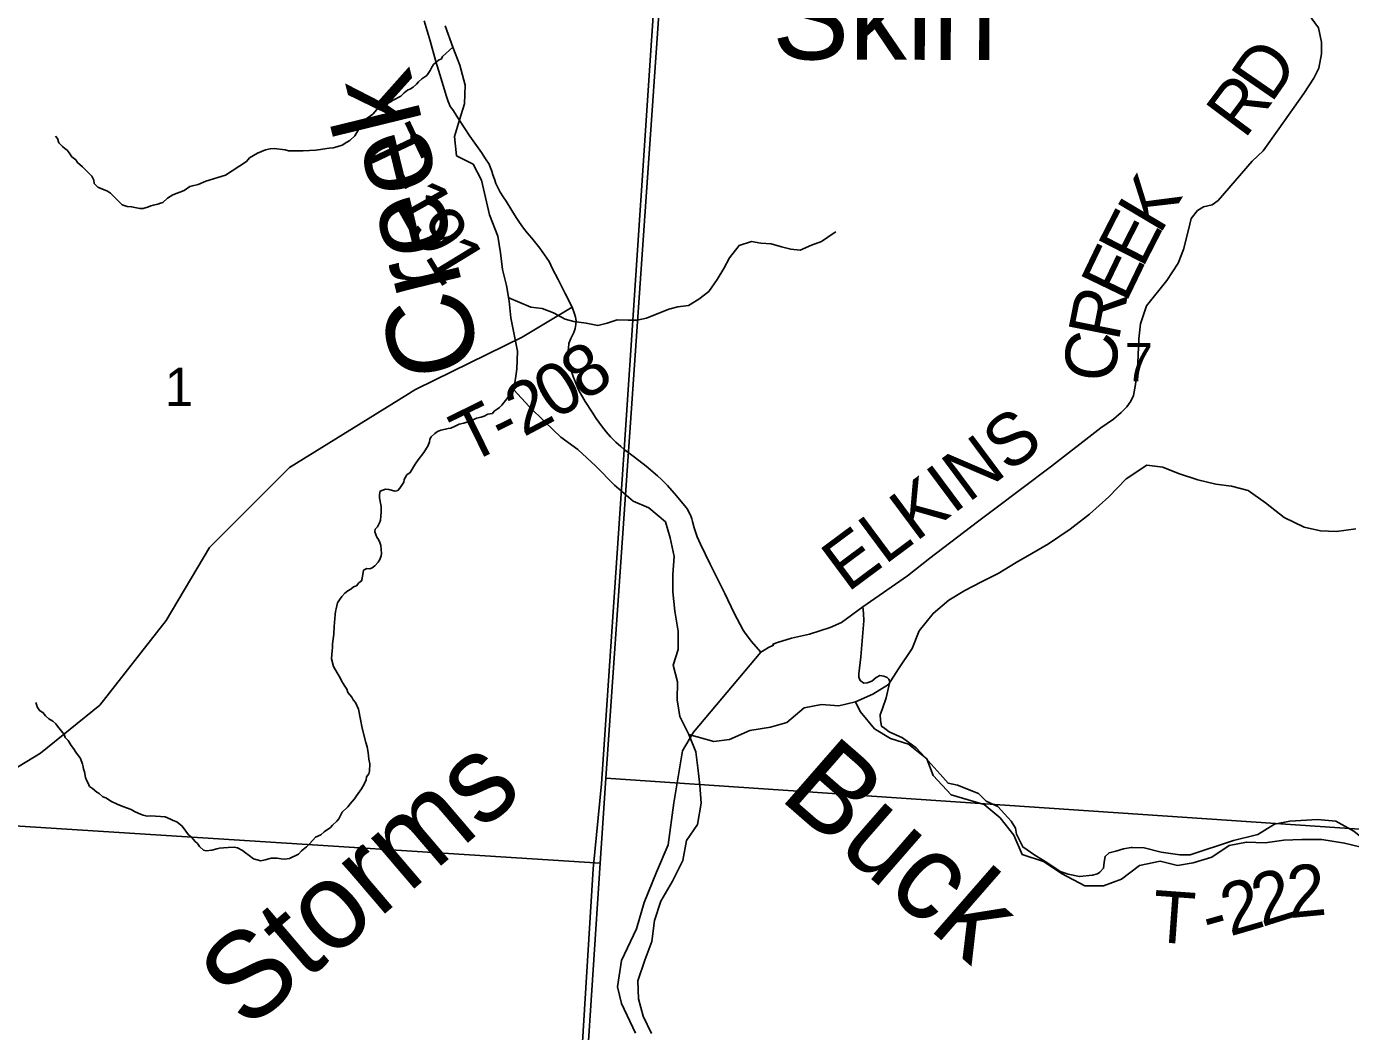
# Model space of a CAD drawing. Extents: x 0 to 34, y 0 to 22.
# Drawn here: x 6.132 to 7.584, y 18.121 to 19.223 of the extents above; entities that cross this region are included whole.
import ezdxf

# ---------------------------------------------------------------- set-up
doc = ezdxf.new("R2010")
doc.units = 0
for name, color, linetype in [('GM_X_Corporation', 7, 'Continuous'), ('GM_X_County_Road', 7, 'Continuous'), ('GM_X_County_Road_Text', 7, 'Continuous'), ('GM_X_Minor_River', 7, 'Continuous'), ('GM_X_Minor_River_Text', 7, 'Continuous'), ('GM_X_Section_Text', 7, 'Continuous'), ('GM_X_Township_Road', 7, 'Continuous'), ('GM_X_Township_Road_Text', 7, 'Continuous')]:
    doc.layers.add(name, color=color, linetype=linetype)

msp = doc.modelspace()

# ---------------------------------------------------------------- linework, layer by layer
at = {"layer": 'GM_X_Corporation'}
for points in [[(8.9, 16.2015), (8.9, 20.2763), (8.59, 20.3005), (8.3805, 20.3169), (8.0028, 20.34), (6.9032, 20.4198), (6.8961, 20.3303), (6.835, 19.4037), (6.824, 19.3005), (6.7876, 18.7583), (6.7629, 18.3924), (6.7536, 18.2991), (6.7043, 17.4985), (6.6962, 17.3669), (6.6852, 17.2401), (6.6249, 16.3344), (7.5782, 16.28), (7.7162, 16.2721), (7.873, 16.2628)], [(7.9347, 19.3346), (7.864, 18.3242), (6.7676, 18.3985), (6.8303, 19.3047), (6.8376, 19.4096)], [(5.8355, 19.3781), (6.8303, 19.3047), (6.7676, 18.3985), (6.7615, 18.3053), (5.775, 18.3681)], [(6.7676, 18.3985), (7.864, 18.3242), (7.7921, 17.3025), (6.6999, 17.3699), (6.7615, 18.3053)], [(5.775, 18.3681), (6.7615, 18.3053), (6.6999, 17.3699), (6.6918, 17.2464), (5.6845, 17.321)]]:
    msp.add_lwpolyline(points, close=True, dxfattribs=at)
msp.add_lwpolyline([(6.7043, 17.4985), (6.7536, 18.2991), (6.7629, 18.3924), (6.7876, 18.7583), (6.824, 19.3005), (6.5423, 19.3229), (5.9419, 19.3649), (5.6539, 19.3859), (5.0201, 19.4401), (4.8375, 19.4557), (3.8692, 19.5228), (3.8201, 19.5262), (3.0215, 19.5789), (2.5886, 19.6074), (2.105, 19.6393), (2.1, 19.6396), (2.1, 16.1353)], dxfattribs=at)
at = {"layer": 'GM_X_County_Road'}
msp.add_lwpolyline([(6.8001, 18.1189), (6.7846, 18.1516), (6.7804, 18.1699), (6.7846, 18.1988), (6.8014, 18.2333), (6.8098, 18.2622), (6.8231, 18.2953), (6.836, 18.3253), (6.8421, 18.3714), (6.8518, 18.4286), (6.8637, 18.4488), (6.9377, 18.5367), (6.9411, 18.539), (6.9461, 18.5417), (6.9514, 18.5442), (6.9508, 18.5454), (6.9559, 18.5472), (6.9712, 18.5519), (6.9908, 18.5563), (7.0136, 18.5638), (7.0259, 18.569), (7.0492, 18.5864), (7.0984, 18.6205), (7.1228, 18.6396), (7.175, 18.6794), (7.1957, 18.695), (7.2222, 18.715), (7.2563, 18.7407), (7.3104, 18.7827), (7.3242, 18.7919), (7.3326, 18.7994), (7.3389, 18.8057), (7.3432, 18.8118), (7.3461, 18.8181), (7.3484, 18.8299), (7.3507, 18.8535), (7.3521, 18.8803), (7.3536, 18.8964), (7.3603, 18.9163), (7.3827, 18.944), (7.3949, 18.9631), (7.401, 18.9781), (7.4065, 18.9998), (7.4095, 19.0121), (7.4163, 19.0209), (7.4228, 19.0247), (7.4323, 19.0271), (7.4391, 19.0318), (7.4762, 19.075), (7.4881, 19.0862), (7.5054, 19.1104), (7.533, 19.1492), (7.5438, 19.1658), (7.5493, 19.1767), (7.5523, 19.1927), (7.5522, 19.2055), (7.549, 19.2211), (7.5381, 19.2359)], dxfattribs=at)
at = {"layer": 'GM_X_Minor_River'}
for points in [[(6.6402, 19.0162), (6.6312, 19.0541), (6.6222, 19.0716), (6.604, 19.0808), (6.6018, 19.102), (6.6072, 19.1202), (6.6125, 19.1376), (6.6133, 19.1581), (6.6074, 19.1801), (6.5999, 19.1999), (6.5916, 19.2234)], [(6.5999, 19.1999), (6.5884, 19.1896), (6.5873, 19.187), (6.5842, 19.1855), (6.5815, 19.1833), (6.5788, 19.1807), (6.5769, 19.1781), (6.5749, 19.1743), (6.5714, 19.169), (6.566, 19.1653), (6.5622, 19.162), (6.5599, 19.1593), (6.5564, 19.156), (6.5534, 19.1541), (6.5503, 19.1527), (6.5465, 19.1497), (6.543, 19.146), (6.5346, 19.1419), (6.5311, 19.1397), (6.525, 19.1371), (6.522, 19.1368), (6.5189, 19.1342), (6.512, 19.1264), (6.5035, 19.1204), (6.5004, 19.1167), (6.4977, 19.1106), (6.4957, 19.108), (6.4926, 19.1028), (6.4868, 19.0975), (6.4838, 19.0957), (6.4784, 19.0924), (6.4727, 19.0906), (6.4685, 19.0895), (6.4643, 19.0892), (6.4522, 19.0875), (6.4495, 19.0868), (6.4359, 19.0862), (6.4264, 19.0864), (6.4226, 19.0861), (6.4196, 19.0861), (6.4162, 19.0873), (6.4041, 19.0887), (6.3996, 19.0884), (6.3946, 19.0873), (6.3858, 19.0837), (6.377, 19.0785), (6.3735, 19.0744), (6.3506, 19.0596), (6.3289, 19.0531), (6.3205, 19.0495), (6.3144, 19.048), (6.3117, 19.0473), (6.3052, 19.0429), (6.293, 19.0381), (6.2872, 19.0344), (6.2819, 19.0296), (6.2792, 19.0289), (6.2765, 19.0278), (6.2716, 19.0267), (6.2689, 19.026), (6.2662, 19.0249), (6.2605, 19.0231), (6.2567, 19.0232), (6.2477, 19.0249), (6.2428, 19.0253), (6.2375, 19.0269), (6.2308, 19.0335), (6.2245, 19.0397), (6.2211, 19.042), (6.2132, 19.0452), (6.2106, 19.0464), (6.2068, 19.0503), (6.2062, 19.0541), (6.204, 19.0583), (6.2017, 19.061), (6.1965, 19.066), (6.1939, 19.0687), (6.1883, 19.0734), (6.1865, 19.0764), (6.182, 19.0796), (6.1794, 19.0842), (6.1772, 19.0868), (6.1746, 19.0888), (6.172, 19.0911), (6.1679, 19.095), (6.1664, 19.0996), (6.1642, 19.1023)], [(6.8176, 18.1185), (6.8085, 18.1375), (6.8033, 18.1565), (6.8026, 18.1763), (6.8102, 18.199), (6.8179, 18.2195), (6.821, 18.2423), (6.8278, 18.2635), (6.8408, 18.2855), (6.8522, 18.3082), (6.856, 18.3302), (6.8682, 18.3476), (6.8721, 18.3712), (6.8706, 18.3909), (6.8684, 18.4099), (6.8662, 18.4273), (6.8587, 18.4463), (6.8489, 18.4661), (6.8459, 18.4843), (6.846, 18.5041), (6.8415, 18.5223), (6.8469, 18.5397), (6.8469, 18.5595), (6.8432, 18.5815), (6.841, 18.6028), (6.841, 18.6217), (6.8426, 18.6415), (6.8381, 18.662), (6.8329, 18.6794), (6.8148, 18.6947), (6.7974, 18.7023), (6.777, 18.7198), (6.7566, 18.7404), (6.737, 18.7587), (6.7181, 18.7724), (6.7008, 18.7891), (6.6834, 18.8059), (6.6668, 18.8241), (6.6699, 18.8469), (6.6707, 18.8666), (6.6633, 18.903), (6.6618, 18.9213), (6.6588, 18.9387), (6.6544, 18.9562), (6.6521, 18.9744), (6.6492, 18.9926), (6.6402, 19.0162)], [(6.6611, 18.9252), (6.6854, 18.9147), (6.6979, 18.9135), (6.7104, 18.9086), (6.7229, 18.9018), (6.7327, 18.8991), (6.746, 18.8972), (6.7589, 18.8949), (6.7691, 18.8972), (6.7801, 18.901), (6.7922, 18.9006), (6.802, 18.9006), (6.8122, 18.9029), (6.8368, 18.9127), (6.8467, 18.9154), (6.8584, 18.9165), (6.8694, 18.9237), (6.8807, 18.9321), (6.8898, 18.9453), (6.897, 18.9574), (6.9031, 18.9688), (6.9137, 18.9825), (6.9273, 18.987), (6.9375, 18.9851), (6.9489, 18.9843), (6.9602, 18.9809), (6.9704, 18.9783), (6.9807, 18.9775), (6.9932, 18.9828), (7.0041, 18.987), (7.0178, 18.9965), (7.0197, 18.9976)], [(6.6668, 18.8241), (6.6537, 18.8074), (6.651, 18.8048), (6.6483, 18.803), (6.6452, 18.8007), (6.6433, 18.7981), (6.6384, 18.7974), (6.6342, 18.7952), (6.6311, 18.7941), (6.6258, 18.7931), (6.6197, 18.7902), (6.6121, 18.7876), (6.6067, 18.7866), (6.6033, 18.7847), (6.5976, 18.7822), (6.5949, 18.7818), (6.5919, 18.7811), (6.5866, 18.7801), (6.5831, 18.7786), (6.58, 18.7764), (6.5762, 18.7727), (6.5746, 18.77), (6.5742, 18.7674), (6.573, 18.7632), (6.5679, 18.7557), (6.5617, 18.7475), (6.5586, 18.7426), (6.5532, 18.7335), (6.5493, 18.7309), (6.5466, 18.726), (6.5462, 18.723), (6.5419, 18.7166), (6.5396, 18.714), (6.5365, 18.7133), (6.5297, 18.7149), (6.5259, 18.7154), (6.5233, 18.7143), (6.5202, 18.7132), (6.5194, 18.7094), (6.5193, 18.706), (6.5214, 18.6965), (6.5213, 18.6904), (6.5209, 18.6858), (6.5204, 18.6813), (6.5196, 18.6786), (6.5173, 18.6741), (6.5149, 18.6715), (6.5145, 18.6685), (6.5167, 18.6627), (6.5185, 18.66), (6.52, 18.657), (6.5211, 18.6535), (6.5217, 18.6448), (6.5213, 18.6421), (6.52, 18.6383), (6.5181, 18.6353), (6.5142, 18.6312), (6.5116, 18.629), (6.5089, 18.6279), (6.5055, 18.6283), (6.502, 18.6265), (6.5004, 18.6174), (6.4999, 18.6147), (6.4969, 18.6125), (6.4942, 18.6095), (6.4911, 18.6084), (6.488, 18.6058), (6.4846, 18.604), (6.4815, 18.6014), (6.478, 18.5976), (6.4757, 18.5939), (6.4734, 18.5909), (6.4718, 18.584), (6.4713, 18.5814), (6.4709, 18.578), (6.47, 18.5693), (6.4699, 18.5647), (6.4694, 18.5563), (6.468, 18.5457), (6.468, 18.5415), (6.4675, 18.5385), (6.467, 18.5294), (6.4691, 18.521), (6.4732, 18.5141), (6.4754, 18.5102), (6.479, 18.5033), (6.4813, 18.4995), (6.4838, 18.496), (6.4849, 18.4926), (6.489, 18.4872), (6.4905, 18.4845), (6.4931, 18.4814), (6.4963, 18.4742), (6.4988, 18.4627), (6.5005, 18.4532), (6.5044, 18.4375), (6.5058, 18.4329), (6.5069, 18.4268), (6.5079, 18.4192), (6.5089, 18.4143)], [(6.661, 18.8107), (6.661, 18.8108)], [(7.5898, 18.6718), (7.5686, 18.6689), (7.5512, 18.6697), (7.5331, 18.6735), (7.5112, 18.6842), (7.4908, 18.7002), (7.4719, 18.7139), (7.4537, 18.7185), (7.4363, 18.7209), (7.4167, 18.7255), (7.3955, 18.7324), (7.3781, 18.7393), (7.3607, 18.7416), (7.3379, 18.7265), (7.319, 18.7068), (7.2977, 18.6879), (7.2765, 18.6713), (7.2529, 18.6554), (7.2347, 18.6448), (7.2173, 18.635), (7.1976, 18.6229), (7.1794, 18.6139), (7.1612, 18.6041), (7.1437, 18.5935), (7.1263, 18.5791), (7.1111, 18.5602), (7.1035, 18.5405), (7.0883, 18.5185), (7.0776, 18.5011), (7.0602, 18.4905), (7.0412, 18.4822), (7.023, 18.4777), (7.0041, 18.4793), (6.9852, 18.4756), (6.9662, 18.4597), (6.948, 18.4544), (6.9253, 18.4507), (6.9033, 18.4409), (6.8859, 18.4387), (6.8587, 18.4463)], [(6.5089, 18.4143), (6.5084, 18.4063), (6.5076, 18.4033), (6.5053, 18.3999), (6.5048, 18.3968), (6.5025, 18.3919), (6.4997, 18.3867), (6.4943, 18.3792), (6.492, 18.3758), (6.4873, 18.3702), (6.4846, 18.3672), (6.4784, 18.3612), (6.4749, 18.354), (6.4726, 18.3514), (6.468, 18.3469), (6.4657, 18.3443), (6.4587, 18.3395), (6.4553, 18.3365), (6.4492, 18.3339), (6.443, 18.3268), (6.4395, 18.3231), (6.4341, 18.319), (6.4307, 18.3152), (6.4207, 18.3105), (6.4158, 18.3098), (6.4116, 18.3102), (6.4071, 18.3107), (6.4007, 18.3108), (6.398, 18.3101), (6.3942, 18.309), (6.3893, 18.308), (6.3813, 18.31), (6.3765, 18.3139), (6.3727, 18.3166), (6.3694, 18.3193), (6.3637, 18.3221), (6.36, 18.3229), (6.3535, 18.3226), (6.3486, 18.322), (6.344, 18.3217), (6.341, 18.3209), (6.3357, 18.3195), (6.3296, 18.3189), (6.3266, 18.3197), (6.3221, 18.3235), (6.3199, 18.327), (6.3173, 18.329), (6.3132, 18.334), (6.3102, 18.3363), (6.3073, 18.3405), (6.3032, 18.3459), (6.2972, 18.3506), (6.2931, 18.3522), (6.2904, 18.3534), (6.2844, 18.3561), (6.2689, 18.3571), (6.2647, 18.3568), (6.2602, 18.3581), (6.2576, 18.3589), (6.255, 18.36), (6.2508, 18.362), (6.2474, 18.364), (6.2422, 18.366), (6.2361, 18.368), (6.232, 18.3699), (6.2256, 18.3731), (6.2193, 18.377), (6.2163, 18.3782), (6.2121, 18.3817), (6.2095, 18.3833), (6.2047, 18.3871), (6.2017, 18.3895), (6.2002, 18.3929), (6.1984, 18.3964), (6.1973, 18.3994), (6.1959, 18.4055), (6.1948, 18.4082), (6.1945, 18.4109), (6.1938, 18.4139), (6.1916, 18.4201), (6.1864, 18.427), (6.1839, 18.4312), (6.1813, 18.4343), (6.1783, 18.4397), (6.175, 18.4431), (6.1739, 18.4462), (6.1665, 18.4555), (6.1646, 18.4581), (6.1613, 18.4609), (6.1568, 18.4636), (6.1534, 18.4667), (6.1505, 18.4706), (6.1471, 18.4725), (6.1445, 18.476), (6.1427, 18.4813)], [(7.5956, 18.3227), (7.5774, 18.3273), (7.5525, 18.3312), (7.5305, 18.3312), (7.5108, 18.3305), (7.4904, 18.3276), (7.4699, 18.3284), (7.451, 18.3246), (7.432, 18.3118), (7.4116, 18.3058), (7.3942, 18.3028), (7.3753, 18.3074), (7.3525, 18.3029), (7.3328, 18.2878), (7.3131, 18.2803), (7.2927, 18.2803), (7.267, 18.2941), (7.2473, 18.307), (7.2239, 18.3147), (7.2149, 18.336), (7.1998, 18.355), (7.1824, 18.3695), (7.165, 18.3748), (7.1461, 18.3802), (7.1265, 18.4015), (7.1197, 18.4198), (7.0994, 18.4358), (7.0797, 18.4419), (7.0623, 18.4526), (7.0465, 18.4716), (7.0412, 18.4822)]]:
    msp.add_lwpolyline(points, dxfattribs=at)
at = {"layer": 'GM_X_Township_Road'}
for points in [[(6.7878, 18.7589), (6.7839, 18.762), (6.7787, 18.7668), (6.7727, 18.7726), (6.7679, 18.7782), (6.7627, 18.7847), (6.7569, 18.7929), (6.7527, 18.7996), (6.7448, 18.8113), (6.7381, 18.8236), (6.7368, 18.826), (6.7324, 18.837), (6.7321, 18.8378), (6.7275, 18.8518), (6.7268, 18.856), (6.7262, 18.8615), (6.7261, 18.8657), (6.7265, 18.8698), (6.7272, 18.8751), (6.7294, 18.8804), (6.7324, 18.8872), (6.734, 18.8916), (6.7348, 18.896), (6.7349, 18.8998), (6.7344, 18.904), (6.7333, 18.9075), (6.7307, 18.9147), (6.723, 18.9297), (6.7153, 18.9453), (6.7093, 18.9568), (6.7055, 18.9649), (6.6953, 18.9795), (6.6865, 18.9906), (6.6815, 18.9965), (6.6775, 19.0014), (6.673, 19.0075), (6.6693, 19.0133), (6.6644, 19.0209), (6.6582, 19.0309), (6.6549, 19.0358), (6.6519, 19.041), (6.6491, 19.0462), (6.6471, 19.0504), (6.6456, 19.055), (6.6437, 19.0601), (6.6425, 19.0638), (6.6413, 19.0677), (6.6396, 19.0716), (6.6358, 19.0774), (6.6312, 19.0845), (6.6184, 19.1024), (6.6062, 19.1213), (6.5997, 19.1312), (6.5987, 19.1328), (6.5971, 19.135), (6.5957, 19.1376), (6.5947, 19.1403), (6.5928, 19.1457), (6.5856, 19.17), (6.5814, 19.184), (6.5749, 19.2067), (6.5686, 19.2289)], [(6.5605, 18.8253), (6.676, 18.8818), (6.7307, 18.9147)], [(5.9566, 18.2896), (6.0001, 18.3383), (6.015, 18.3469), (6.0652, 18.3759), (6.1478, 18.426), (6.2129, 18.4786), (6.2855, 18.5713), (6.333, 18.6514), (6.4207, 18.7391), (6.5069, 18.7924), (6.5513, 18.8198), (6.5583, 18.8242), (6.5605, 18.8253)], [(6.9377, 18.5367), (6.9271, 18.5488), (6.9195, 18.5586), (6.9182, 18.5607), (6.9084, 18.5795), (6.8979, 18.6009), (6.8821, 18.6332), (6.8713, 18.655), (6.8679, 18.6629), (6.8666, 18.6664), (6.8645, 18.6728), (6.8625, 18.68), (6.8619, 18.6829), (6.8609, 18.686), (6.8606, 18.6868), (6.8566, 18.6939), (6.8555, 18.6952), (6.8449, 18.7082), (6.8352, 18.7195), (6.8285, 18.7258), (6.8242, 18.7298), (6.8118, 18.7406), (6.7991, 18.7505), (6.7878, 18.7589)], [(7.0492, 18.5864), (7.0501, 18.5793), (7.0505, 18.5711), (7.0471, 18.5314), (7.0448, 18.5129), (7.0448, 18.5092), (7.0466, 18.5055), (7.0505, 18.5028), (7.0542, 18.5031), (7.0591, 18.505), (7.0641, 18.5087), (7.068, 18.511), (7.0722, 18.5105), (7.0762, 18.5087), (7.0773, 18.5076)], [(7.0773, 18.5076), (7.0779, 18.5071), (7.079, 18.5041), (7.078, 18.4993), (7.0751, 18.4865), (7.0711, 18.4748), (7.0685, 18.4679), (7.0689, 18.4618), (7.0699, 18.4555), (7.0735, 18.453), (7.0784, 18.4494), (7.0928, 18.4427), (7.1077, 18.4316), (7.1178, 18.4213), (7.1341, 18.403), (7.1428, 18.3929), (7.1531, 18.3909), (7.1761, 18.3818), (7.1845, 18.3734), (7.1973, 18.3673), (7.2047, 18.3593), (7.212, 18.3512), (7.2167, 18.3438), (7.2177, 18.337), (7.2248, 18.3231), (7.2379, 18.3142), (7.2509, 18.306), (7.2658, 18.2961), (7.2746, 18.2932), (7.2868, 18.2906), (7.3013, 18.2921), (7.3066, 18.2936), (7.3091, 18.2953), (7.3133, 18.2997), (7.314, 18.3064), (7.315, 18.3127), (7.3194, 18.3168), (7.3266, 18.3186), (7.3353, 18.321), (7.3437, 18.3224), (7.3446, 18.3224)], [(7.3446, 18.3224), (7.3577, 18.3221), (7.3765, 18.3175), (7.3969, 18.3146), (7.4082, 18.3146), (7.4559, 18.3303), (7.4825, 18.3368), (7.5007, 18.3482), (7.5174, 18.3512), (7.5478, 18.3531), (7.5679, 18.3512), (7.5877, 18.3405), (7.6089, 18.3234), (7.6401, 18.2983), (7.6598, 18.2896), (7.678, 18.2842), (7.6928, 18.2789), (7.7076, 18.2747), (7.7243, 18.2683), (7.735, 18.2599), (7.7445, 18.2439), (7.7505, 18.2314), (7.7653, 18.2219)]]:
    msp.add_lwpolyline(points, dxfattribs=at)

# ---------------------------------------------------------------- texts
at = {"layer": 'GM_X_County_Road_Text'}
for s, height, rotation, p in [('D', 0.0568, 55.441, (7.4971, 19.1374)), ('R', 0.0568, 53.2136, (7.4678, 19.0981)), ('K', 0.0568, 59.28, (7.3749, 18.9935)), ('E', 0.0568, 62.8389, (7.3559, 18.9565)), ('E', 0.0568, 64.2888, (7.3377, 18.9186)), ('R', 0.0568, 78.714, (7.3297, 18.8764)), ('C', 0.0568, 84.7784, (7.3257, 18.8315)), ('ELKINS', 0.05682, 36.6473, (7.0327, 18.6015))]:
    msp.add_text(s, height=height, rotation=rotation, dxfattribs=at).set_placement(p)
at = {"layer": 'GM_X_Minor_River_Text'}
for s, height, rotation, p in [('Skin', 0.09469, 359.754, (6.9499, 19.1867)), ('Creek', 0.09472, 103.7568, (6.6325, 18.8505)), ('Buck', 0.09473, 318.9031, (6.9561, 18.3772)), ('Storms', 0.09472, 40.5166, (6.3743, 18.1208))]:
    msp.add_text(s, height=height, rotation=rotation, dxfattribs=at).set_placement(p)
at = {"layer": 'GM_X_Section_Text'}
for s, p in [('7', (7.3363, 18.8337)), ('1', (6.2842, 18.8065))]:
    msp.add_text(s, height=0.0419, rotation=0, dxfattribs=at).set_placement(p)
at = {"layer": 'GM_X_Township_Road_Text'}
for s, rotation, p in [('T', 295.3973, (6.5007, 19.0964)), ('-', 299.3802, (6.5209, 19.0542)), ('1', 299.4462, (6.5324, 19.0338)), ('9', 299.8398, (6.5498, 19.0029)), ('1', 301.4077, (6.5681, 18.9711)), ('8', 34.93, (6.7445, 18.8107)), ('0', 31.4425, (6.7115, 18.7904)), ('2', 27.955, (6.6773, 18.7721)), ('T', 26.2112, (6.6166, 18.7422)), ('-', 26.2112, (6.6547, 18.7609)), ('2', 5.5454, (7.5171, 18.245)), ('2', 17.418, (7.4867, 18.2351)), ('T', 355.8663, (7.3653, 18.2193)), ('2', 16.2432, (7.4519, 18.2249)), ('-', 15.8124, (7.429, 18.2185))]:
    msp.add_text(s, height=0.0568, rotation=rotation, dxfattribs=at).set_placement(p)

doc.saveas('drawing.dxf')
